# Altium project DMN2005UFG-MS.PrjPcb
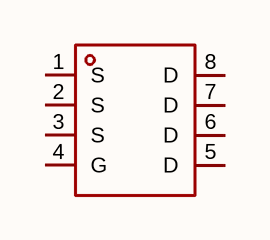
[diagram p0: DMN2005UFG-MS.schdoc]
1 sheet, 1 parts. Net scope: global (net labels, ports and power ports of the same name join across sheets).

## Sheet DMN2005UFG-MS.schdoc
size 127 x 101 mm

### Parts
Q?  dmn2005ufg-ms  [POWERPAK-1212-8_L3.0-W3.0-P0.65-LS3.3-BL]  (value not drawn)

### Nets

Not connected (* = marked no-connect by the designer): Q? 1(S) 2(S) 3(S) 4(G) 5(D) 6(D) 7(D) 8(D)

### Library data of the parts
Q? = dmn2005ufg-ms: 数量:1个N沟道;漏源电压(Vdss):20V;连续漏极电流(Id):60A;导通电阻(RDS(on)):4mΩ@4.5V;耗散功率(Pd):15W;阈值电压(Vgs(th)):700mV;; Manufacturer: MSKSEMI(美森科); AddInBom: yes; ModelId: 74fc8db97a8d4d328d7f3b4acba39a5e; ModelTransform: 129.921,129.921,0,0,0,0,0,0,0; Number: 1个N沟道; Drain to Source Voltage: 20V; Current - Continuous Drain(Id): 60A; Pd - Power Dissipation: 15W; Gate Threshold Voltage (Vgs(th)): 700mV; Gate Charge(Qg): 32nC; Input Capacitance(Ciss): 2.5nF; Reverse Transfer Capacitance (Crss@Vds): 386pF; Type: N沟道; Output Capacitance(Coss): 407pF; Vgs: ±12V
